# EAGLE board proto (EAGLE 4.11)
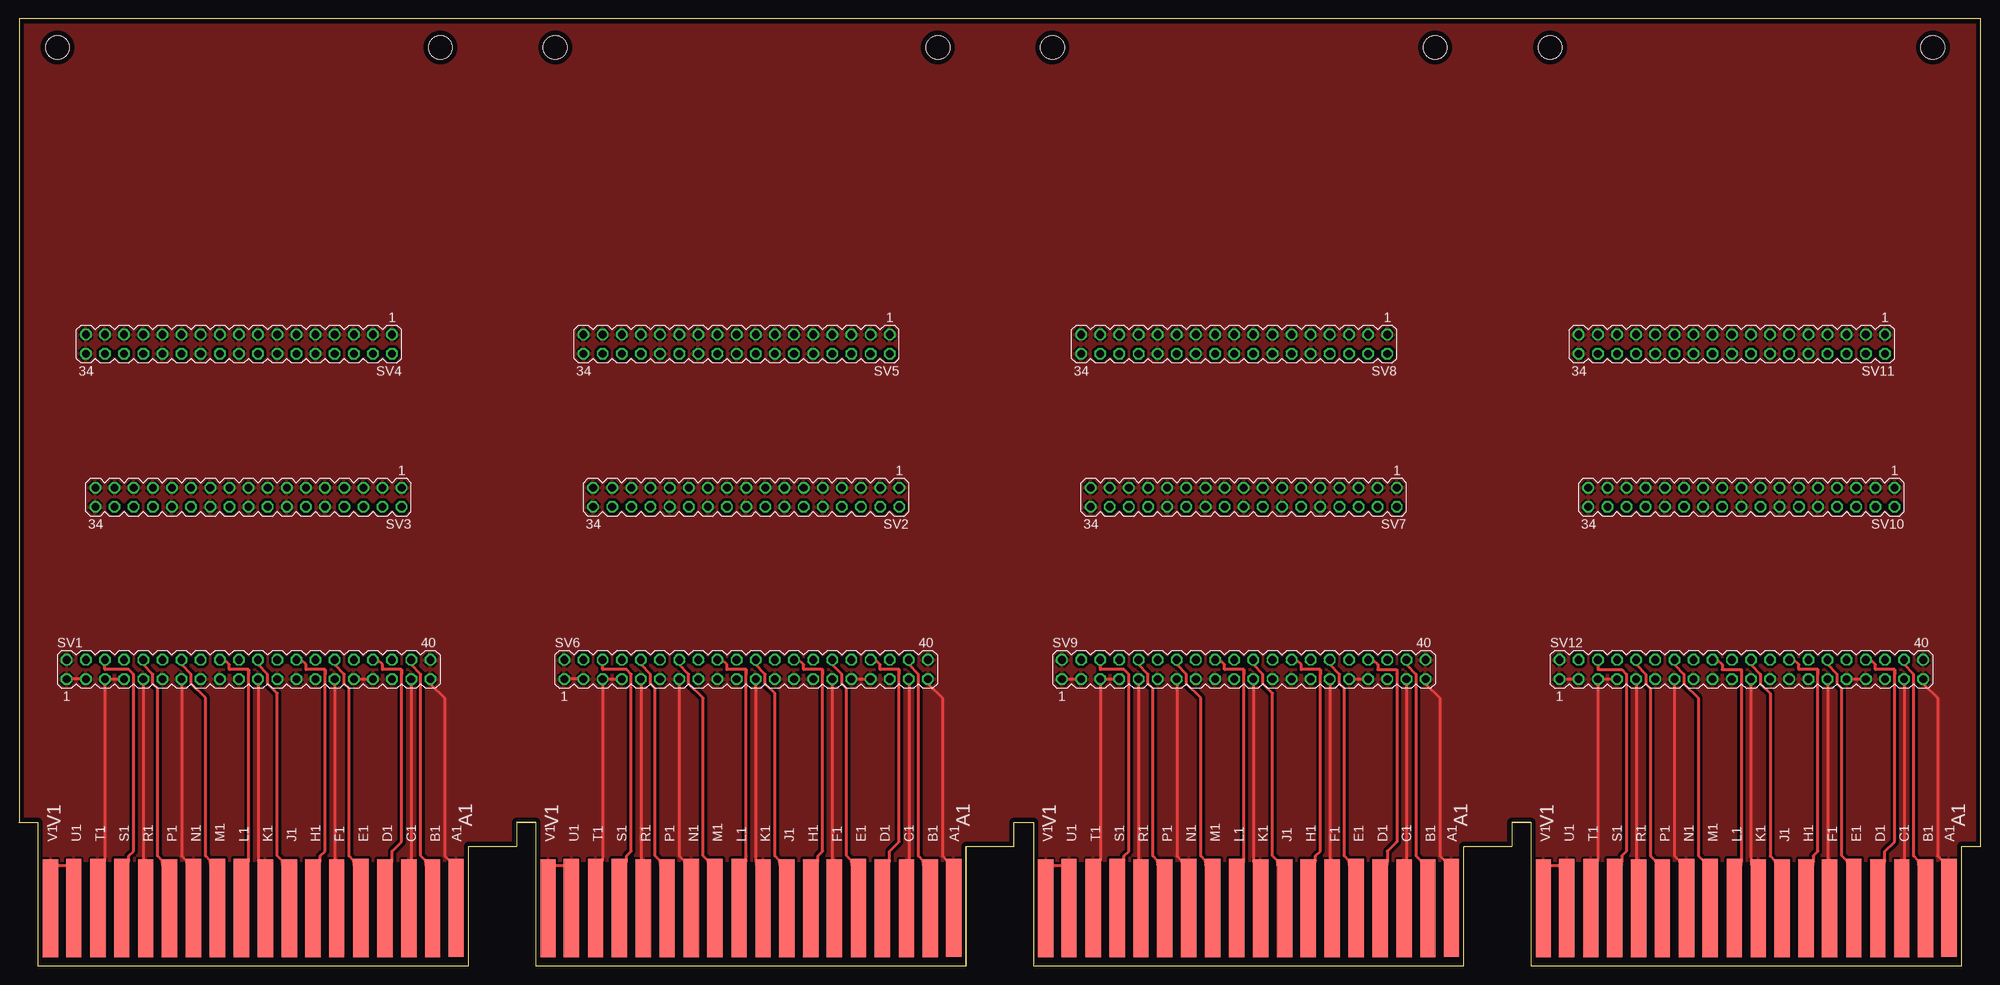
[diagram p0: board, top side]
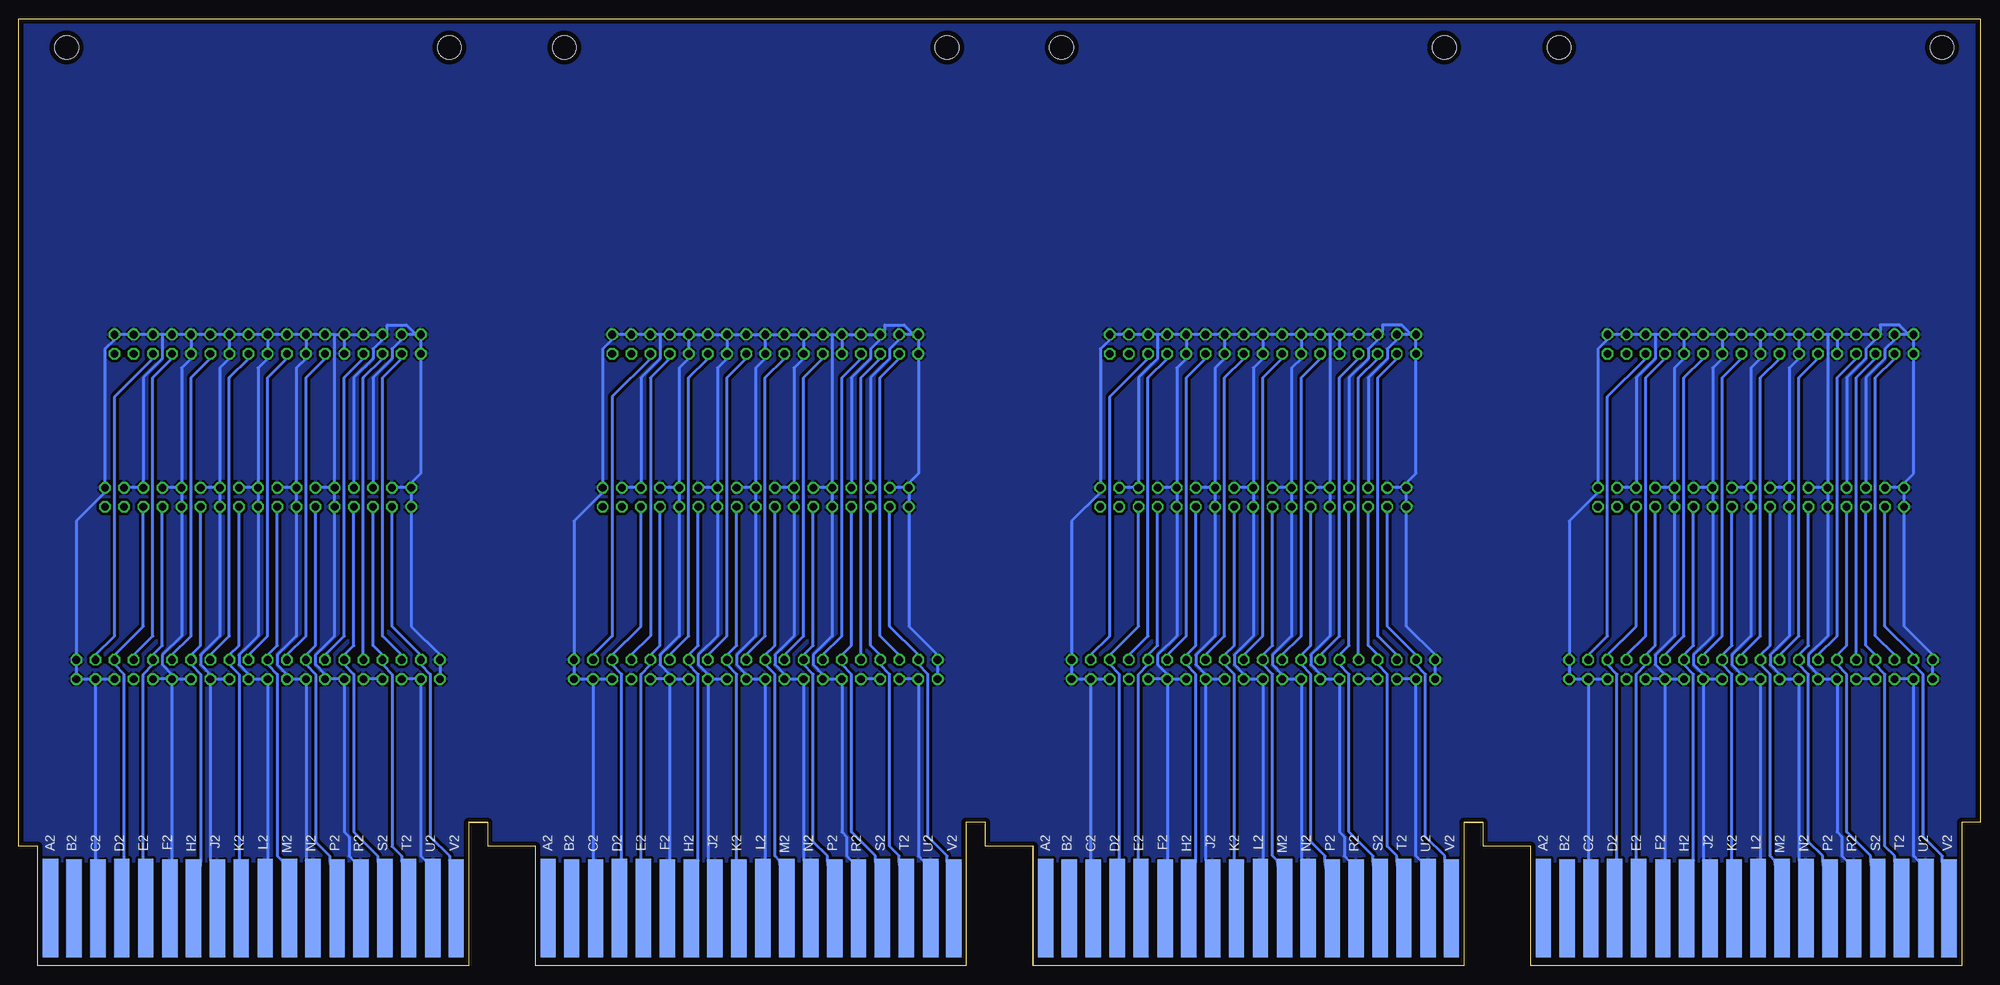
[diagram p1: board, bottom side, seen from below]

Size 260.35 x 125.73 mm. Coordinates in mm from the lower left corner, seen from the top.
Copper layers (1*16): Top 0.035mm / dielectric 1.5mm / Bottom 0.035mm
Design rules "olimex10mil": minimum track width 15mil, minimum drill 24mil, track to track 15mil, track to pad 10mil, pad to pad 10mil, via to via 10mil, smd to smd 10mil, copper to edge 25mil, drill to drill 10mil, minimum pad ring 10mil, minimum via ring 8mil, stop-mask expansion 0mil, vias tented up to drill 0mil, thermal gap 10mil

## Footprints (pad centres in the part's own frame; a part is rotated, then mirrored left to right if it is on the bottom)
DECPROTO = hole 3.175: 203.2,121.92; 254,121.92; 187.96,121.92; 137.16,121.92; 71.171,121.92; 121.971,121.92; 55.931,121.92; 5.131,121.92
MA20-2 = drill 1.016 octagon: 1 -24.13,-1.27; 2 -24.13,1.27; 3 -21.59,-1.27; 4 -21.59,1.27; 5 -19.05,-1.27; 6 -19.05,1.27; 7 -16.51,-1.27; 8 -16.51,1.27; 9 -13.97,-1.27; 10 -13.97,1.27; 11 -11.43,-1.27; 12 -11.43,1.27; 13 -8.89,-1.27; 14 -8.89,1.27; 15 -6.35,-1.27; 16 -6.35,1.27; 17 -3.81,-1.27; 18 -3.81,1.27; 19 -1.27,-1.27; 20 -1.27,1.27; 21 1.27,-1.27; 22 1.27,1.27; 23 3.81,-1.27; 24 3.81,1.27; 25 6.35,-1.27; 26 6.35,1.27; 27 8.89,-1.27; 28 8.89,1.27; 29 11.43,-1.27; 30 11.43,1.27; 31 13.97,-1.27; 32 13.97,1.27; 33 16.51,-1.27; 34 16.51,1.27; 35 19.05,-1.27; 36 19.05,1.27; 37 21.59,-1.27; 38 21.59,1.27; 39 24.13,-1.27; 40 24.13,1.27
MA17-2 = drill 1.016 octagon: 1 -20.32,-1.27; 2 -20.32,1.27; 3 -17.78,-1.27; 4 -17.78,1.27; 5 -15.24,-1.27; 6 -15.24,1.27; 7 -12.7,-1.27; 8 -12.7,1.27; 9 -10.16,-1.27; 10 -10.16,1.27; 11 -7.62,-1.27; 12 -7.62,1.27; 13 -5.08,-1.27; 14 -5.08,1.27; 15 -2.54,-1.27; 16 -2.54,1.27; 17 0,-1.27; 18 0,1.27; 19 2.54,-1.27; 20 2.54,1.27; 21 5.08,-1.27; 22 5.08,1.27; 23 7.62,-1.27; 24 7.62,1.27; 25 10.16,-1.27; 26 10.16,1.27; 27 12.7,-1.27; 28 12.7,1.27; 29 15.24,-1.27; 30 15.24,1.27; 31 17.78,-1.27; 32 17.78,1.27; 33 20.32,-1.27; 34 20.32,1.27
EDGE-CON2 = smd 13.017 x 2.032: A1 7.709,4.207; B1 7.684,7.312; C1 7.684,10.474; D1 7.684,13.665; E1 7.693,16.84; F1 7.668,20.041; H1 7.668,23.19; J1 7.668,26.34; K1 7.668,29.515; L1 7.693,32.69; M1 7.693,35.89; N1 7.693,39.04; P1 7.668,42.24; R1 7.668,45.39; S1 7.693,48.565; T1 7.693,51.74; U1 7.693,54.94; V1 7.668,58.026 | smd 13.017 x 2.032 bottom: A2 7.69,4.207; B2 7.668,7.328; C2 7.668,10.49; D2 7.693,13.665; E2 7.693,16.84; F2 7.642,20.041; H2 7.642,23.19; J2 7.668,26.34; K2 7.668,29.515; L2 7.693,32.69; M2 7.693,35.89; N2 7.693,39.04; P2 7.668,42.24; R2 7.668,45.39; S2 7.693,48.565; T2 7.693,51.74; U2 7.693,54.966; V2 7.668,58.026

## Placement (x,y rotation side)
E$1  [DECPROTO]  0,0 0 top
SV1  [MA20-2]  30.48,39.37 0 top
SV2  [MA17-2]  96.52,62.23 180 top
SV3  [MA17-2]  30.48,62.23 180 top
SV4  [MA17-2]  29.21,82.55 180 top
SV5  [MA17-2]  95.25,82.55 180 top
SV6  [MA20-2]  96.52,39.37 0 top
SV7  [MA17-2]  162.56,62.23 180 top
SV8  [MA17-2]  161.29,82.55 180 top
SV9  [MA20-2]  162.56,39.37 0 top
SV10  [MA17-2]  228.6,62.23 180 top
SV11  [MA17-2]  227.33,82.55 180 top
SV12  [MA20-2]  228.6,39.37 0 top
U$1  [EDGE-CON2]  194.31,0 90 top
U$2  [EDGE-CON2]  62.23,0 90 top
U$3  [EDGE-CON2]  128.27,0 90 top
U$5  [EDGE-CON2]  260.35,0 90 top

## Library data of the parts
E$1 U$1-U$3 U$5 = dec-con
SV1-SV12 = con-lstb

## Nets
-15V: U$2.B2
-15V1: U$3.B2
-15V2: U$1.B2
-15V3: U$5.B2
B1: SV1.38 SV4.6 U$2.B1
B2: SV5.6 SV6.38 U$3.B1
B3: SV8.6 SV9.38 U$1.B1
B4: SV11.6 SV12.38 U$5.B1
D1: SV1.34 SV4.8 U$2.D1
D2: SV1.36 SV3.6 U$2.D2
D3: SV2.6 SV6.36 U$3.D2
D4: SV5.8 SV6.34 U$3.D1
D5: SV7.6 SV9.36 U$1.D2
D6: SV8.8 SV9.34 U$1.D1
D7: SV10.6 SV12.36 U$5.D2
D8: SV11.8 SV12.34 U$5.D1
E1: SV1.30 SV4.12 U$2.E1
E2: SV1.32 SV3.8 U$2.E2
E3: SV2.8 SV6.32 U$3.E2
E4: SV5.12 SV6.30 U$3.E1
E5: SV7.8 SV9.32 U$1.E2
E6: SV8.12 SV9.30 U$1.E1
E7: SV10.8 SV12.32 U$5.E2
E8: SV11.12 SV12.30 U$5.E1
GND: SV1.1 SV1.2 SV1.3 SV1.5 SV1.7 SV1.9 SV1.11 SV1.13 SV1.15 SV1.17 SV1.19 SV1.21 SV1.23 SV1.25 SV1.27 SV1.29 SV1.31 SV1.33 SV1.35 SV1.37 SV1.39 SV1.40 SV2.1 SV2.3 SV2.5 SV2.7 SV2.9 SV2.10 SV2.11 SV2.13 SV2.14 SV2.15 SV2.17 SV2.18 SV2.19 SV2.21 SV2.22 SV2.23 SV2.25 SV2.26 SV2.27 SV2.29 SV2.31 SV2.33 SV2.34 SV3.1 SV3.3 SV3.5 SV3.7 SV3.9 SV3.10 SV3.11 SV3.13 SV3.14 SV3.15 SV3.17 SV3.18 SV3.19 SV3.21 SV3.22 SV3.23 SV3.25 SV3.26 SV3.27 SV3.29 SV3.31 SV3.33 SV3.34 SV4.1 SV4.3 SV4.5 SV4.7 SV4.9 SV4.10 SV4.11 SV4.13 SV4.14 SV4.15 SV4.17 SV4.18 SV4.19 SV4.21 SV4.22 SV4.23 SV4.25 SV4.26 SV4.27 SV4.29 SV4.31 SV4.33 SV4.34 SV5.1 SV5.3 SV5.5 SV5.7 SV5.9 SV5.10 SV5.11 SV5.13 SV5.14 SV5.15 SV5.17 SV5.18 SV5.19 SV5.21 SV5.22 SV5.23 SV5.25 SV5.26 SV5.27 SV5.29 SV5.31 SV5.33 SV5.34 SV6.1 SV6.2 SV6.3 SV6.5 SV6.7 SV6.9 SV6.11 SV6.13 SV6.15 SV6.17 SV6.19 SV6.21 SV6.23 SV6.25 SV6.27 SV6.29 SV6.31 SV6.33 SV6.35 SV6.37 SV6.39 SV6.40 SV7.1 SV7.3 SV7.5 SV7.7 SV7.9 SV7.10 SV7.11 SV7.13 SV7.14 SV7.15 SV7.17 SV7.18 SV7.19 SV7.21 SV7.22 SV7.23 SV7.25 SV7.26 SV7.27 SV7.29 SV7.31 SV7.33 SV7.34 SV8.1 SV8.3 SV8.5 SV8.7 SV8.9 SV8.10 SV8.11 SV8.13 SV8.14 SV8.15 SV8.17 SV8.18 SV8.19 SV8.21 SV8.22 SV8.23 SV8.25 SV8.26 SV8.27 SV8.29 SV8.31 SV8.33 SV8.34 SV9.1 SV9.2 SV9.3 SV9.5 SV9.7 SV9.9 SV9.11 SV9.13 SV9.15 SV9.17 SV9.19 SV9.21 SV9.23 SV9.25 SV9.27 SV9.29 SV9.31 SV9.33 SV9.35 SV9.37 SV9.39 SV9.40 SV10.1 SV10.3 SV10.5 SV10.7 SV10.9 SV10.10 SV10.11 SV10.13 SV10.14 SV10.15 SV10.17 SV10.18 SV10.19 SV10.21 SV10.22 SV10.23 SV10.25 SV10.26 SV10.27 SV10.29 SV10.31 SV10.33 SV10.34 SV11.1 SV11.3 SV11.5 SV11.7 SV11.9 SV11.10 SV11.11 SV11.13 SV11.14 SV11.15 SV11.17 SV11.18 SV11.19 SV11.21 SV11.22 SV11.23 SV11.25 SV11.26 SV11.27 SV11.29 SV11.31 SV11.33 SV11.34 SV12.1 SV12.2 SV12.3 SV12.5 SV12.7 SV12.9 SV12.11 SV12.13 SV12.15 SV12.17 SV12.19 SV12.21 SV12.23 SV12.25 SV12.27 SV12.29 SV12.31 SV12.33 SV12.35 SV12.37 SV12.39 SV12.40 U$1.A1 U$1.C1 U$1.C2 U$1.F1 U$1.F2 U$1.J2 U$1.K1 U$1.L2 U$1.N1 U$1.N2 U$1.R1 U$1.R2 U$1.T1 U$1.U1 U$1.U2 U$1.V1 U$2.A1 U$2.C1 U$2.C2 U$2.F1 U$2.F2 U$2.J2 U$2.K1 U$2.L2 U$2.N1 U$2.N2 U$2.R1 U$2.R2 U$2.T1 U$2.U1 U$2.U2 U$2.V1 U$3.A1 U$3.C1 U$3.C2 U$3.F1 U$3.F2 U$3.J2 U$3.K1 U$3.L2 U$3.N1 U$3.N2 U$3.R1 U$3.R2 U$3.T1 U$3.U1 U$3.U2 U$3.V1 U$5.A1 U$5.C1 U$5.C2 U$5.F1 U$5.F2 U$5.J2 U$5.K1 U$5.L2 U$5.N1 U$5.N2 U$5.R1 U$5.R2 U$5.T1 U$5.U1 U$5.U2 U$5.V1
H1: SV1.26 SV4.16 U$2.H1
H2: SV1.28 SV3.12 U$2.H2
H3: SV2.12 SV6.28 U$3.H2
H4: SV5.16 SV6.26 U$3.H1
H5: SV7.12 SV9.28 U$1.H2
H6: SV8.16 SV9.26 U$1.H1
H7: SV10.12 SV12.28 U$5.H2
H8: SV11.16 SV12.26 U$5.H1
J1: SV1.22 SV4.20 U$2.J1
J2: SV5.20 SV6.22 U$3.J1
J3: SV8.20 SV9.22 U$1.J1
J4: SV11.20 SV12.22 U$5.J1
K1: SV2.16 SV6.24 U$3.K2
K2: SV1.24 SV3.16 U$2.K2
K3: SV7.16 SV9.24 U$1.K2
K4: SV10.16 SV12.24 U$5.K2
L1: SV1.18 SV4.24 U$2.L1
L2: SV5.24 SV6.18 U$3.L1
L3: SV8.24 SV9.18 U$1.L1
L4: SV11.24 SV12.18 U$5.L1
M1: SV1.14 SV4.28 U$2.M1
M2: SV1.20 SV3.20 U$2.M2
M3: SV2.20 SV6.20 U$3.M2
M4: SV5.28 SV6.14 U$3.M1
M5: SV7.20 SV9.20 U$1.M2
M6: SV8.28 SV9.14 U$1.M1
M7: SV10.20 SV12.20 U$5.M2
M8: SV11.28 SV12.14 U$5.M1
P1: SV1.10 SV4.30 U$2.P1
P2: SV1.16 SV3.24 U$2.P2
P3: SV2.24 SV6.16 U$3.P2
P4: SV5.30 SV6.10 U$3.P1
P5: SV7.24 SV9.16 U$1.P2
P6: SV8.30 SV9.10 U$1.P1
P7: SV10.24 SV12.16 U$5.P2
P8: SV11.30 SV12.10 U$5.P1
S1: SV1.6 SV4.32 U$2.S1
S2: SV1.12 SV3.28 U$2.S2
S3: SV2.28 SV6.12 U$3.S2
S4: SV5.32 SV6.6 U$3.S1
S5: SV7.28 SV9.12 U$1.S2
S6: SV8.32 SV9.6 U$1.S1
S7: SV10.28 SV12.12 U$5.S2
S8: SV11.32 SV12.6 U$5.S1
T1: SV2.30 SV6.8 U$3.T2
T2: SV1.8 SV3.30 U$2.T2
T3: SV7.30 SV9.8 U$1.T2
T4: SV10.30 SV12.8 U$5.T2
V1: SV2.32 SV6.4 U$3.V2
V2: SV1.4 SV3.32 U$2.V2
V3: SV7.32 SV9.4 U$1.V2
V4: SV10.32 SV12.4 U$5.V2
VCC: U$2.A2
VCC1: U$3.A2
VCC2: U$1.A2
VCC3: U$5.A2

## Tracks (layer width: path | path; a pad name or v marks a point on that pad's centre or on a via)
B1
  Top 0.381: SV1.38 52.07,40.01 53.34,38.74 53.34,14.61 53.98,13.97 U$2.B1
  Bottom 0.381: SV1.38 52.07,41.28 49.53,43.82 49.53,75.57 44.45,80.65 SV4.6
B2
  Top 0.381: SV6.38 118.11,40.01 119.38,38.74 119.38,14.61 120.02,13.97 U$3.B1
  Bottom 0.381: SV6.38 118.11,41.28 115.57,43.82 115.57,75.57 110.49,80.65 SV5.6
B3
  Top 0.381: SV9.38 184.15,40.01 185.42,38.74 185.42,14.61 186.06,13.97 U$1.B1
  Bottom 0.381: SV9.38 184.15,41.28 181.61,43.82 181.61,75.57 176.53,80.65 SV8.6
B4
  Top 0.381: SV12.38 250.19,40.01 251.46,38.74 251.46,14.61 252.09,13.97 U$5.B1
  Bottom 0.381: SV12.38 250.19,41.28 247.65,43.82 247.65,75.57 242.57,80.65 SV11.6
D1
  Top 0.381: 50.8,39.37 50.8,16.51 49.53,15.24 49.53,13.97 U$2.D1 | 50.8,39.37 50.8,38.74 | 50.8,39.37 48.26,39.37 48.26,40.01 47.62,40.64 SV1.34
  Bottom 0.381: SV1.34 46.99,41.28 44.45,43.82 44.45,78.11 41.91,80.65 SV4.8
D2
  Bottom 0.381: SV3.6 45.72,60.33 45.72,45.09 49.53,41.28 SV1.36 49.53,40.01 48.26,38.74 48.26,13.97 U$2.D2
D3
  Bottom 0.381: SV2.6 111.76,60.33 111.76,45.09 115.57,41.28 SV6.36 115.57,40.01 114.3,38.74 114.3,13.97 U$3.D2
D4
  Top 0.381: 116.84,39.37 116.84,16.51 115.57,15.24 115.57,13.97 U$3.D1 | 116.84,39.37 116.84,38.74 | 116.84,39.37 114.3,39.37 114.3,40.01 113.67,40.64 SV6.34
  Bottom 0.381: SV6.34 113.03,41.28 110.49,43.82 110.49,78.11 107.95,80.65 SV5.8
D5
  Bottom 0.381: SV7.6 177.8,60.33 177.8,45.09 181.61,41.28 SV9.36 181.61,40.01 180.34,38.74 180.34,13.97 U$1.D2
D6
  Top 0.381: 182.88,39.37 182.88,16.51 181.61,15.24 181.61,13.97 U$1.D1 | 182.88,39.37 182.88,38.74 | 182.88,39.37 180.34,39.37 180.34,40.01 179.71,40.64 SV9.34
  Bottom 0.381: SV9.34 179.07,41.28 176.53,43.82 176.53,78.11 173.99,80.65 SV8.8
D7
  Bottom 0.381: SV10.6 243.84,60.33 243.84,45.09 247.65,41.28 SV12.36 247.65,40.01 246.38,38.74 246.38,13.97 U$5.D2
D8
  Top 0.381: 248.92,39.37 248.92,16.51 247.65,15.24 247.65,13.97 U$5.D1 | 248.92,39.37 248.92,38.74 | 248.92,39.37 246.38,39.37 246.38,40.01 245.75,40.64 SV12.34
  Bottom 0.381: SV12.34 245.11,41.28 242.57,43.82 242.57,78.11 240.03,80.65 SV11.8
E1
  Top 0.381: SV1.30 41.91,40.01 43.18,38.74 43.18,37.47 43.81,36.83 43.81,14.61 44.45,13.97 U$2.E1
  Bottom 0.381: SV1.30 41.91,41.28 39.37,43.82 39.37,78.11 36.83,80.65 SV4.12
E2
  Bottom 0.381: SV3.8 43.18,60.33 43.18,42.55 44.45,41.28 SV1.32 44.45,40.01 45.72,38.74 45.72,13.97 U$2.E2
E3
  Bottom 0.381: SV2.8 109.22,60.33 109.22,42.55 110.49,41.28 SV6.32 110.49,40.01 111.76,38.74 111.76,13.97 U$3.E2
E4
  Top 0.381: SV6.30 107.95,40.01 109.22,38.74 109.22,37.47 109.86,36.83 109.86,14.61 110.49,13.97 U$3.E1
  Bottom 0.381: SV6.30 107.95,41.28 105.41,43.82 105.41,78.11 102.87,80.65 SV5.12
E5
  Bottom 0.381: SV7.8 175.26,60.33 175.26,42.55 176.53,41.28 SV9.32 176.53,40.01 177.8,38.74 177.8,13.97 U$1.E2
E6
  Top 0.381: SV9.30 173.99,40.01 175.26,38.74 175.26,37.47 175.9,36.83 175.9,14.61 176.53,13.97 U$1.E1
  Bottom 0.381: SV9.30 173.99,41.28 171.45,43.82 171.45,78.11 168.91,80.65 SV8.12
E7
  Bottom 0.381: SV10.8 241.3,60.33 241.3,42.55 242.57,41.28 SV12.32 242.57,40.01 243.84,38.74 243.84,13.97 U$5.E2
E8
  Top 0.381: SV12.30 240.03,40.01 241.3,38.74 241.3,37.47 241.94,36.83 241.94,14.61 242.57,13.97 U$5.E1
  Bottom 0.381: SV12.30 240.03,41.28 237.49,43.82 237.49,78.11 234.95,80.65 SV11.12
GND
  Top 0.381: 11.43,13.97 11.43,37.47 SV1.5 12.06,38.1 13.34,38.1 SV1.7 | SV1.9 16.51,37.47 16.51,13.97 U$2.R1 | SV1.3 8.26,38.1 6.99,38.1 SV1.1 | 52.07,13.97 52.07,37.47 SV1.37 | SV1.39 54.61,37.47 56.52,35.56 56.52,14.61 57.15,13.97 U$2.A1 | SV1.21 31.75,37.47 31.75,13.97 U$2.K1 | SV1.33 46.35,38.1 45.09,38.1 SV1.31 | SV1.29 41.91,37.47 41.91,13.97 U$2.F1 | SV1.13 21.59,37.47 21.59,14.61 22.23,13.97 U$2.N1 | 4,13.97 3.81,13.97 U$2.V1 5.08,13.34 6.35,13.34 U$2.U1 | U$2.T1 10.16,13.97 10.29,13.97 | U$2.C1 51.44,13.97 51.55,13.97 | 77.47,13.97 77.47,37.47 SV6.5 78.11,38.1 79.38,38.1 SV6.7 | SV6.9 82.55,37.47 82.55,13.97 U$3.R1 | SV6.3 74.3,38.1 73.03,38.1 SV6.1 | 118.11,13.97 118.11,37.47 SV6.37 | SV6.39 120.65,37.47 122.56,35.56 122.56,14.61 123.19,13.97 U$3.A1 | SV6.21 97.79,37.47 97.79,13.97 U$3.K1 | SV6.33 112.39,38.1 111.12,38.1 SV6.31 | SV6.29 107.95,37.47 107.95,13.97 U$3.F1 | SV6.13 87.63,37.47 87.63,14.61 88.27,13.97 U$3.N1 | 70.04,13.97 69.85,13.97 U$3.V1 71.12,13.34 72.39,13.34 U$3.U1 | U$3.T1 76.2,13.97 76.33,13.97 | U$3.C1 117.47,13.97 117.59,13.97 | 143.51,13.97 143.51,37.47 SV9.5 144.15,38.1 145.41,38.1 SV9.7 | SV9.9 148.59,37.47 148.59,13.97 U$1.R1 | SV9.3 140.34,38.1 139.06,38.1 SV9.1 | 184.15,13.97 184.15,37.47 SV9.37 | SV9.39 186.69,37.47 188.59,35.56 188.59,14.61 189.23,13.97 U$1.A1 | SV9.21 163.83,37.47 163.83,13.97 U$1.K1 | SV9.33 178.44,38.1 177.16,38.1 SV9.31 | SV9.29 173.99,37.47 173.99,13.97 U$1.F1 | SV9.13 153.67,37.47 153.67,14.61 154.31,13.97 U$1.N1 | 136.08,13.97 135.89,13.97 U$1.V1 137.16,13.34 138.43,13.34 U$1.U1 | U$1.T1 142.24,13.97 142.37,13.97 | U$1.C1 183.51,13.97 183.63,13.97
  Top 0.381: 209.55,13.97 209.55,37.47 SV12.5 210.19,38.1 211.46,38.1 SV12.7 | SV12.9 214.63,37.47 214.63,13.97 U$5.R1 | SV12.3 206.38,38.1 205.1,38.1 SV12.1 | 250.19,13.97 250.19,37.47 SV12.37 | SV12.39 252.73,37.47 254.63,35.56 254.63,14.61 255.27,13.97 U$5.A1 | SV12.21 229.87,37.47 229.87,13.97 U$5.K1 | SV12.33 244.47,38.1 243.21,38.1 SV12.31 | SV12.29 240.03,37.47 240.03,13.97 U$5.F1 | SV12.13 219.71,37.47 219.71,14.61 220.34,13.97 U$5.N1 | 202.12,13.97 201.93,13.97 U$5.V1 203.2,13.34 204.47,13.34 U$5.U1 | U$5.T1 208.28,13.97 208.41,13.97 | U$5.C1 249.56,13.97 249.67,13.97
  Bottom 0.381: SV1.5 10.79,38.1 9.53,38.1 SV1.3 8.89,37.47 8.89,14.61 8.26,13.97 | SV1.9 15.88,38.1 14.61,38.1 SV1.7 | SV1.1 6.35,38.74 6.35,40.01 SV1.2 6.35,41.28 10.16,45.09 10.16,60.33 SV3.34 10.16,61.6 10.16,62.87 SV3.33 | SV3.31 12.06,63.5 10.79,63.5 SV3.33 | SV4.33 8.89,83.19 8.89,81.92 SV4.34 8.89,80.65 8.89,65.41 10.16,64.14 SV3.33 | SV3.29 15.24,64.14 15.24,78.11 12.7,80.65 12.7,81.92 11.43,83.19 SV4.31 10.79,83.82 9.53,83.82 | SV4.33 9.53,83.82 | SV1.37 52.7,38.1 53.98,38.1 SV1.39 54.61,38.74 54.61,40.01 SV1.40 54.61,41.28 54.61,59.06 50.8,62.87 SV3.1 50.8,64.14 50.8,81.92 49.53,83.19 SV4.1 48.9,83.82 47.62,83.82 SV4.3 46.35,83.82 45.09,83.82 SV4.5 43.81,83.82 43.18,83.82 | SV1.35 50.16,38.1 51.44,38.1 SV1.37 | 52.07,13.97 52.07,37.47 SV1.37 | SV1.29 42.55,38.1 43.81,38.1 SV1.31 | SV1.27 40.01,38.1 41.27,38.1 SV1.29 | SV1.29 41.91,37.47 41.91,13.97 U$2.F2 | SV1.25 36.2,38.1 34.92,38.1 SV1.23 | 36.83,13.97 36.83,37.47 SV1.25 | 24.13,13.97 24.13,37.47 SV1.15 24.77,38.1 26.04,38.1 SV1.17 26.67,38.74 27.94,40.01 27.94,41.28 25.4,43.82 25.4,60.33 SV3.22 25.4,61.6 25.4,62.87 SV3.21 | SV3.13 35.56,62.87 35.56,61.6 SV3.14 35.56,60.33 35.56,43.82 38.1,41.28 38.1,40.01 36.83,38.74 SV1.25 | SV3.11 37.47,63.5 36.2,63.5 SV3.13 | SV4.13 34.29,83.19 34.29,81.92 SV4.14 34.29,80.65 35.56,79.38 35.56,64.14 SV3.13 | SV4.13 33.66,83.82 32.38,83.82 SV4.15 31.11,83.82 29.84,83.82 SV4.17 | SV3.17 30.48,62.87 30.48,61.6 SV3.18 30.48,60.33 30.48,43.82 33.02,41.28 33.02,40.01 31.75,38.74 SV1.21 31.11,38.1 29.84,38.1 SV1.19 29.21,37.47 29.21,13.97 U$2.L2 | SV3.15 32.38,63.5 31.11,63.5 SV3.17
  Bottom 0.381: SV4.17 29.21,83.19 29.21,81.92 SV4.18 29.21,80.65 30.48,79.38 30.48,64.14 SV3.17 | SV4.17 28.57,83.82 27.3,83.82 SV4.19 26.04,83.82 24.77,83.82 SV4.21 | SV3.3 47.62,63.5 46.35,63.5 SV3.5 45.72,64.14 45.72,78.11 43.18,80.65 43.18,83.82 | 43.18,83.82 42.55,83.82 SV4.7 41.27,83.82 40.01,83.82 SV4.9 | SV3.9 40.64,62.87 40.64,61.6 SV3.10 40.64,60.33 40.64,43.82 43.18,41.28 43.18,40.01 41.91,38.74 SV1.29 | SV3.7 42.55,63.5 41.27,63.5 SV3.9 | SV4.9 39.37,83.19 39.37,81.92 SV4.10 39.37,80.65 40.64,79.38 40.64,64.14 SV3.9 | SV4.9 38.73,83.82 37.47,83.82 SV4.11 36.2,83.82 34.92,83.82 SV4.13 | SV3.23 22.23,63.5 20.95,63.5 SV3.25 | SV3.25 20.32,62.87 20.32,61.6 SV3.26 20.32,60.33 20.32,43.82 22.86,41.28 22.86,40.01 21.59,38.74 SV1.13 20.95,38.1 19.68,38.1 SV1.11 19.05,37.47 19.05,17.78 18.41,17.15 18.41,14.61 17.78,13.97 | SV4.26 19.05,81.92 19.05,83.19 SV4.25 | SV4.25 18.41,83.82 17.14,83.82 SV4.27 15.88,83.82 14.61,83.82 SV4.29 | SV3.27 17.78,64.14 17.78,78.11 15.24,80.65 15.24,81.92 13.97,83.19 SV4.29 | SV3.19 27.3,63.5 26.04,63.5 SV3.21 | SV4.21 24.13,83.19 24.13,81.92 SV4.22 24.13,80.65 25.4,79.38 25.4,64.14 SV3.21 | SV4.21 23.5,83.82 22.23,83.82 SV4.23 20.95,83.82 20.32,83.82 | 20.32,83.82 19.68,83.82 SV4.25 | 20.32,83.82 20.32,64.14 SV3.25 | 9.53,83.82 10.79,85.09 13.34,85.09 13.34,83.82 SV4.29 | SV4.33 9.53,83.82 | U$2.U2 6.99,13.97 7.06,13.97 | U$2.R1 16.51,13.97 16.64,13.97 | U$2.N1 22.86,13.97 22.99,13.97 | U$2.J2 35.56,13.97 35.69,13.97 | U$2.C2 51.44,13.97 51.54,13.97 | SV6.5 76.83,38.1 75.56,38.1 SV6.3 74.93,37.47 74.93,14.61 74.3,13.97 | SV6.9 81.92,38.1 80.64,38.1 SV6.7
  Bottom 0.381: SV6.1 72.39,38.74 72.39,40.01 SV6.2 72.39,41.28 76.2,45.09 76.2,60.33 SV2.34 76.2,61.6 76.2,62.87 SV2.33 | SV2.31 78.11,63.5 76.83,63.5 SV2.33 | SV5.33 74.93,83.19 74.93,81.92 SV5.34 74.93,80.65 74.93,65.41 76.2,64.14 SV2.33 | SV2.29 81.28,64.14 81.28,78.11 78.74,80.65 78.74,81.92 77.47,83.19 SV5.31 76.83,83.82 75.56,83.82 | SV5.33 75.56,83.82 | SV6.37 118.75,38.1 120.02,38.1 SV6.39 120.65,38.74 120.65,40.01 SV6.40 120.65,41.28 120.65,59.06 116.84,62.87 SV2.1 116.84,64.14 116.84,81.92 115.57,83.19 SV5.1 114.94,83.82 113.67,83.82 SV5.3 112.39,83.82 111.12,83.82 SV5.5 109.86,83.82 109.22,83.82 | SV6.35 116.2,38.1 117.47,38.1 SV6.37 | 118.11,13.97 118.11,37.47 SV6.37 | SV6.29 108.58,38.1 109.86,38.1 SV6.31 | SV6.27 106.05,38.1 107.31,38.1 SV6.29 | SV6.29 107.95,37.47 107.95,13.97 U$3.F2 | SV6.25 102.23,38.1 100.97,38.1 SV6.23 | 102.87,13.97 102.87,37.47 SV6.25 | 90.17,13.97 90.17,37.47 SV6.15 90.81,38.1 92.08,38.1 SV6.17 92.71,38.74 93.98,40.01 93.98,41.28 91.44,43.82 91.44,60.33 SV2.22 91.44,61.6 91.44,62.87 SV2.21 | SV2.13 101.6,62.87 101.6,61.6 SV2.14 101.6,60.33 101.6,43.82 104.14,41.28 104.14,40.01 102.87,38.74 SV6.25 | SV2.11 103.5,63.5 102.23,63.5 SV2.13 | SV5.13 100.33,83.19 100.33,81.92 SV5.14 100.33,80.65 101.6,79.38 101.6,64.14 SV2.13 | SV5.13 99.69,83.82 98.42,83.82 SV5.15 97.16,83.82 95.89,83.82 SV5.17 | SV2.17 96.52,62.87 96.52,61.6 SV2.18 96.52,60.33 96.52,43.82 99.06,41.28 99.06,40.01 97.79,38.74 SV6.21 97.16,38.1 95.89,38.1 SV6.19 95.25,37.47 95.25,13.97 U$3.L2 | SV2.15 98.42,63.5 97.16,63.5 SV2.17 | SV5.17 95.25,83.19 95.25,81.92 SV5.18 95.25,80.65 96.52,79.38 96.52,64.14 SV2.17
  Bottom 0.381: SV5.17 94.61,83.82 93.34,83.82 SV5.19 92.08,83.82 90.81,83.82 SV5.21 | SV2.3 113.67,63.5 112.39,63.5 SV2.5 111.76,64.14 111.76,78.11 109.22,80.65 109.22,83.82 | 109.22,83.82 108.58,83.82 SV5.7 107.31,83.82 106.05,83.82 SV5.9 | SV2.9 106.68,62.87 106.68,61.6 SV2.10 106.68,60.33 106.68,43.82 109.22,41.28 109.22,40.01 107.95,38.74 SV6.29 | SV2.7 108.58,63.5 107.31,63.5 SV2.9 | SV5.9 105.41,83.19 105.41,81.92 SV5.10 105.41,80.65 106.68,79.38 106.68,64.14 SV2.9 | SV5.9 104.78,83.82 103.5,83.82 SV5.11 102.23,83.82 100.97,83.82 SV5.13 | SV2.23 88.27,63.5 87,63.5 SV2.25 | SV2.25 86.36,62.87 86.36,61.6 SV2.26 86.36,60.33 86.36,43.82 88.9,41.28 88.9,40.01 87.63,38.74 SV6.13 87,38.1 85.72,38.1 SV6.11 85.09,37.47 85.09,17.78 84.45,17.15 84.45,14.61 83.82,13.97 | SV5.26 85.09,81.92 85.09,83.19 SV5.25 | SV5.25 84.45,83.82 83.19,83.82 SV5.27 81.92,83.82 80.64,83.82 SV5.29 | SV2.27 83.82,64.14 83.82,78.11 81.28,80.65 81.28,81.92 80.01,83.19 SV5.29 | SV2.19 93.34,63.5 92.08,63.5 SV2.21 | SV5.21 90.17,83.19 90.17,81.92 SV5.22 90.17,80.65 91.44,79.38 91.44,64.14 SV2.21 | SV5.21 89.53,83.82 88.27,83.82 SV5.23 87,83.82 86.36,83.82 | 86.36,83.82 85.72,83.82 SV5.25 | 86.36,83.82 86.36,64.14 SV2.25 | 75.56,83.82 76.83,85.09 79.38,85.09 79.38,83.82 SV5.29 | SV5.33 75.56,83.82 | U$3.U2 73.03,13.97 73.1,13.97 | U$3.R1 82.55,13.97 82.68,13.97 | U$3.N1 88.9,13.97 89.03,13.97 | U$3.J2 101.6,13.97 101.73,13.97 | U$3.C2 117.47,13.97 117.58,13.97 | SV9.5 142.88,38.1 141.6,38.1 SV9.3 140.97,37.47 140.97,14.61 140.34,13.97 | SV9.9 147.96,38.1 146.69,38.1 SV9.7 | SV9.1 138.43,38.74 138.43,40.01 SV9.2 138.43,41.28 142.24,45.09 142.24,60.33 SV7.34 142.24,61.6 142.24,62.87 SV7.33
  Bottom 0.381: SV7.31 144.15,63.5 142.88,63.5 SV7.33 | SV8.33 140.97,83.19 140.97,81.92 SV8.34 140.97,80.65 140.97,65.41 142.24,64.14 SV7.33 | SV7.29 147.32,64.14 147.32,78.11 144.78,80.65 144.78,81.92 143.51,83.19 SV8.31 142.88,83.82 141.6,83.82 | 141.6,83.82 SV8.33 | SV9.37 184.78,38.1 186.06,38.1 SV9.39 186.69,38.74 186.69,40.01 SV9.40 186.69,41.28 186.69,59.06 182.88,62.87 SV7.1 182.88,64.14 182.88,81.92 181.61,83.19 SV8.1 180.97,83.82 179.71,83.82 SV8.3 178.44,83.82 177.16,83.82 SV8.5 175.9,83.82 175.26,83.82 | SV9.35 182.25,38.1 183.51,38.1 SV9.37 | 184.15,13.97 184.15,37.47 SV9.37 | SV9.29 174.62,38.1 175.9,38.1 SV9.31 | SV9.27 172.09,38.1 173.35,38.1 SV9.29 | SV9.29 173.99,37.47 173.99,13.97 U$1.F2 | SV9.25 168.28,38.1 167,38.1 SV9.23 | 168.91,13.97 168.91,37.47 SV9.25 | 156.21,13.97 156.21,37.47 SV9.15 156.84,38.1 158.12,38.1 SV9.17 158.75,38.74 160.02,40.01 160.02,41.28 157.48,43.82 157.48,60.33 SV7.22 157.48,61.6 157.48,62.87 SV7.21 | SV7.13 167.64,62.87 167.64,61.6 SV7.14 167.64,60.33 167.64,43.82 170.18,41.28 170.18,40.01 168.91,38.74 SV9.25 | SV7.11 169.54,63.5 168.28,63.5 SV7.13 | SV8.13 166.37,83.19 166.37,81.92 SV8.14 166.37,80.65 167.64,79.38 167.64,64.14 SV7.13 | SV8.13 165.74,83.82 164.47,83.82 SV8.15 163.19,83.82 161.93,83.82 SV8.17 | SV7.17 162.56,62.87 162.56,61.6 SV7.18 162.56,60.33 162.56,43.82 165.1,41.28 165.1,40.01 163.83,38.74 SV9.21 163.19,38.1 161.93,38.1 SV9.19 161.29,37.47 161.29,13.97 U$1.L2 | SV7.15 164.47,63.5 163.19,63.5 SV7.17 | SV8.17 161.29,83.19 161.29,81.92 SV8.18 161.29,80.65 162.56,79.38 162.56,64.14 SV7.17
  Bottom 0.381: SV8.17 160.66,83.82 159.38,83.82 SV8.19 158.12,83.82 156.84,83.82 SV8.21 | SV7.3 179.71,63.5 178.44,63.5 SV7.5 177.8,64.14 177.8,78.11 175.26,80.65 175.26,83.82 | 175.26,83.82 174.62,83.82 SV8.7 173.35,83.82 172.09,83.82 SV8.9 | SV7.9 172.72,62.87 172.72,61.6 SV7.10 172.72,60.33 172.72,43.82 175.26,41.28 175.26,40.01 173.99,38.74 SV9.29 | SV7.7 174.62,63.5 173.35,63.5 SV7.9 | SV8.9 171.45,83.19 171.45,81.92 SV8.10 171.45,80.65 172.72,79.38 172.72,64.14 SV7.9 | SV8.9 170.81,83.82 169.54,83.82 SV8.11 168.28,83.82 167,83.82 SV8.13 | SV7.23 154.31,63.5 153.03,63.5 SV7.25 | SV7.25 152.4,62.87 152.4,61.6 SV7.26 152.4,60.33 152.4,43.82 154.94,41.28 154.94,40.01 153.67,38.74 SV9.13 153.03,38.1 151.76,38.1 SV9.11 151.13,37.47 151.13,17.78 150.5,17.15 150.5,14.61 149.86,13.97 | SV8.26 151.13,81.92 151.13,83.19 SV8.25 | SV8.25 150.5,83.82 149.22,83.82 SV8.27 147.96,83.82 146.69,83.82 SV8.29 | SV7.27 149.86,64.14 149.86,78.11 147.32,80.65 147.32,81.92 146.05,83.19 SV8.29 | SV7.19 159.38,63.5 158.12,63.5 SV7.21 | SV8.21 156.21,83.19 156.21,81.92 SV8.22 156.21,80.65 157.48,79.38 157.48,64.14 SV7.21 | SV8.21 155.57,83.82 154.31,83.82 SV8.23 153.03,83.82 152.4,83.82 | 152.4,83.82 151.76,83.82 SV8.25 | 152.4,83.82 152.4,64.14 SV7.25 | 141.6,83.82 142.88,85.09 145.41,85.09 145.41,83.82 SV8.29 | 141.6,83.82 SV8.33 | U$1.U2 139.06,13.97 139.14,13.97 | U$1.R1 148.59,13.97 148.72,13.97 | U$1.N1 154.94,13.97 155.07,13.97 | U$1.J2 167.64,13.97 167.77,13.97 | U$1.C2 183.51,13.97 183.62,13.97 | SV12.5 208.91,38.1 207.65,38.1 SV12.3 207.01,37.47 207.01,14.61 206.38,13.97 | SV12.9 214,38.1 212.72,38.1 SV12.7
  Bottom 0.381: SV12.1 204.47,38.74 204.47,40.01 SV12.2 204.47,41.28 208.28,45.09 208.28,60.33 SV10.34 208.28,61.6 208.28,62.87 SV10.33 | SV10.31 210.19,63.5 208.91,63.5 SV10.33 | SV11.33 207.01,83.19 207.01,81.92 SV11.34 207.01,80.65 207.01,65.41 208.28,64.14 SV10.33 | SV10.29 213.36,64.14 213.36,78.11 210.82,80.65 210.82,81.92 209.55,83.19 SV11.31 208.91,83.82 207.65,83.82 | 207.65,83.82 SV11.33 | SV12.37 250.82,38.1 252.09,38.1 SV12.39 252.73,38.74 252.73,40.01 SV12.40 252.73,41.28 252.73,59.06 248.92,62.87 SV10.1 248.92,64.14 248.92,81.92 247.65,83.19 SV11.1 247.01,83.82 245.75,83.82 SV11.3 244.47,83.82 243.21,83.82 SV11.5 241.94,83.82 241.3,83.82 | SV12.35 248.28,38.1 249.56,38.1 SV12.37 | 250.19,13.97 250.19,37.47 SV12.37 | SV12.29 240.66,38.1 241.94,38.1 SV12.31 | SV12.27 238.12,38.1 239.4,38.1 SV12.29 | SV12.29 240.03,37.47 240.03,13.97 U$5.F2 | SV12.25 234.31,38.1 233.04,38.1 SV12.23 | 234.95,13.97 234.95,37.47 SV12.25 | 222.25,13.97 222.25,37.47 SV12.15 222.88,38.1 224.16,38.1 SV12.17 224.79,38.74 226.06,40.01 226.06,41.28 223.52,43.82 223.52,60.33 SV10.22 223.52,61.6 223.52,62.87 SV10.21 | SV10.13 233.68,62.87 233.68,61.6 SV10.14 233.68,60.33 233.68,43.82 236.22,41.28 236.22,40.01 234.95,38.74 SV12.25 | SV10.11 235.59,63.5 234.31,63.5 SV10.13 | SV11.13 232.41,83.19 232.41,81.92 SV11.14 232.41,80.65 233.68,79.38 233.68,64.14 SV10.13 | SV11.13 231.78,83.82 230.5,83.82 SV11.15 229.24,83.82 227.97,83.82 SV11.17 | SV10.17 228.6,62.87 228.6,61.6 SV10.18 228.6,60.33 228.6,43.82 231.14,41.28 231.14,40.01 229.87,38.74 SV12.21 229.24,38.1 227.97,38.1 SV12.19 227.33,37.47 227.33,13.97 U$5.L2
  Bottom 0.381: SV10.15 230.5,63.5 229.24,63.5 SV10.17 | SV11.17 227.33,83.19 227.33,81.92 SV11.18 227.33,80.65 228.6,79.38 228.6,64.14 SV10.17 | SV11.17 226.69,83.82 225.43,83.82 SV11.19 224.16,83.82 222.88,83.82 SV11.21 | SV10.3 245.75,63.5 244.47,63.5 SV10.5 243.84,64.14 243.84,78.11 241.3,80.65 241.3,83.82 | 241.3,83.82 240.66,83.82 SV11.7 239.4,83.82 238.12,83.82 SV11.9 | SV10.9 238.76,62.87 238.76,61.6 SV10.10 238.76,60.33 238.76,43.82 241.3,41.28 241.3,40.01 240.03,38.74 SV12.29 | SV10.7 240.66,63.5 239.4,63.5 SV10.9 | SV11.9 237.49,83.19 237.49,81.92 SV11.10 237.49,80.65 238.76,79.38 238.76,64.14 SV10.9 | SV11.9 236.85,83.82 235.59,83.82 SV11.11 234.31,83.82 233.04,83.82 SV11.13 | SV10.23 220.34,63.5 219.07,63.5 SV10.25 | SV10.25 218.44,62.87 218.44,61.6 SV10.26 218.44,60.33 218.44,43.82 220.98,41.28 220.98,40.01 219.71,38.74 SV12.13 219.07,38.1 217.81,38.1 SV12.11 217.17,37.47 217.17,17.78 216.53,17.15 216.53,14.61 215.9,13.97 | SV11.26 217.17,81.92 217.17,83.19 SV11.25 | SV11.25 216.53,83.82 215.26,83.82 SV11.27 214,83.82 212.72,83.82 SV11.29 | SV10.27 215.9,64.14 215.9,78.11 213.36,80.65 213.36,81.92 212.09,83.19 SV11.29 | SV10.19 225.43,63.5 224.16,63.5 SV10.21 | SV11.21 222.25,83.19 222.25,81.92 SV11.22 222.25,80.65 223.52,79.38 223.52,64.14 SV10.21 | SV11.21 221.62,83.82 220.34,83.82 SV11.23 219.07,83.82 218.44,83.82 | 218.44,83.82 217.81,83.82 SV11.25 | 218.44,83.82 218.44,64.14 SV10.25 | 207.65,83.82 208.91,85.09 211.46,85.09 211.46,83.82 SV11.29 | 207.65,83.82 SV11.33 | U$5.U2 205.1,13.97 205.18,13.97 | U$5.R1 214.63,13.97 214.76,13.97 | U$5.N1 220.98,13.97 221.11,13.97
  Bottom 0.381: U$5.J2 233.68,13.97 233.81,13.97 | U$5.C2 249.56,13.97 249.66,13.97
  pour Bottom (isolate 0.305): 2.54,13.97 2.54,19.05 0,19.05 0,125.73 66.04,125.73 66.04,16.51 59.69,16.51 59.69,13.97
  pour Top (isolate 0.305): 2.54,13.97 2.54,19.05 0,19.05 0,125.73 66.04,125.73 66.04,16.51 59.69,16.51 59.69,13.97
  pour Bottom (isolate 0.305): 68.58,13.97 68.58,19.05 66.04,19.05 66.04,125.73 132.08,125.73 132.08,16.51 125.73,16.51 125.73,13.97
  pour Top (isolate 0.305): 68.58,13.97 68.58,19.05 66.04,19.05 66.04,125.73 132.08,125.73 132.08,16.51 125.73,16.51 125.73,13.97
  pour Bottom (isolate 0.305): 134.62,13.97 134.62,19.05 132.08,19.05 132.08,125.73 198.12,125.73 198.12,16.51 191.77,16.51 191.77,13.97
  pour Top (isolate 0.305): 134.62,13.97 134.62,19.05 132.08,19.05 132.08,125.73 198.12,125.73 198.12,16.51 191.77,16.51 191.77,13.97
  pour Bottom (isolate 0.305): 200.66,13.97 200.66,19.05 198.12,19.05 198.12,125.73 260.35,125.73 260.35,16.51 257.81,16.51 257.81,13.97
  pour Top (isolate 0.305): 200.66,13.97 200.66,19.05 198.12,19.05 198.12,125.73 260.35,125.73 260.35,16.51 257.81,16.51 257.81,13.97
H1
  Top 0.381: 40.64,39.37 40.64,15.24 40.01,14.61 40.01,13.97 U$2.H1 | 40.64,39.37 40.64,38.74 | 40.64,39.37 38.1,39.37 38.1,40.01 37.47,40.64 SV1.26
  Bottom 0.381: SV1.26 36.83,41.28 34.29,43.82 34.29,78.11 31.75,80.65 SV4.16
H2
  Bottom 0.381: SV3.12 38.1,60.33 38.1,42.55 39.37,41.28 SV1.28 39.37,40.01 38.1,38.74 38.1,13.97 U$2.H2
H3
  Bottom 0.381: SV2.12 104.14,60.33 104.14,42.55 105.41,41.28 SV6.28 105.41,40.01 104.14,38.74 104.14,13.97 U$3.H2
H4
  Top 0.381: 106.68,39.37 106.68,15.24 106.05,14.61 106.05,13.97 U$3.H1 | 106.68,39.37 106.68,38.74 | 106.68,39.37 104.14,39.37 104.14,40.01 103.5,40.64 SV6.26
  Bottom 0.381: SV6.26 102.87,41.28 100.33,43.82 100.33,78.11 97.79,80.65 SV5.16
H5
  Bottom 0.381: SV7.12 170.18,60.33 170.18,42.55 171.45,41.28 SV9.28 171.45,40.01 170.18,38.74 170.18,13.97 U$1.H2
H6
  Top 0.381: 172.72,39.37 172.72,15.24 172.09,14.61 172.09,13.97 U$1.H1 | 172.72,39.37 172.72,38.74 | 172.72,39.37 170.18,39.37 170.18,40.01 169.54,40.64 SV9.26
  Bottom 0.381: SV9.26 168.91,41.28 166.37,43.82 166.37,78.11 163.83,80.65 SV8.16
H7
  Bottom 0.381: SV10.12 236.22,60.33 236.22,42.55 237.49,41.28 SV12.28 237.49,40.01 236.22,38.74 236.22,13.97 U$5.H2
H8
  Top 0.381: 238.76,39.37 238.76,15.24 238.12,14.61 238.12,13.97 U$5.H1 | 238.76,39.37 238.76,38.74 | 238.76,39.37 236.22,39.37 236.22,40.01 235.59,40.64 SV12.26
  Bottom 0.381: SV12.26 234.95,41.28 232.41,43.82 232.41,78.11 229.87,80.65 SV11.16
J1
  Top 0.381: SV1.22 31.75,40.01 33.02,38.74 33.02,37.47 34.29,36.2 34.29,14.61 34.92,13.97 U$2.J1
  Bottom 0.381: SV1.22 31.75,41.28 29.21,43.82 29.21,78.11 26.67,80.65 SV4.20
J2
  Top 0.381: SV6.22 97.79,40.01 99.06,38.74 99.06,37.47 100.33,36.2 100.33,14.61 100.97,13.97 U$3.J1
  Bottom 0.381: SV6.22 97.79,41.28 95.25,43.82 95.25,78.11 92.71,80.65 SV5.20
J3
  Top 0.381: SV9.22 163.83,40.01 165.1,38.74 165.1,37.47 166.37,36.2 166.37,14.61 167,13.97 U$1.J1
  Bottom 0.381: SV9.22 163.83,41.28 161.29,43.82 161.29,78.11 158.75,80.65 SV8.20
J4
  Top 0.381: SV12.22 229.87,40.01 231.14,38.74 231.14,37.47 232.41,36.2 232.41,14.61 233.04,13.97 U$5.J1
  Bottom 0.381: SV12.22 229.87,41.28 227.33,43.82 227.33,78.11 224.79,80.65 SV11.20
K1
  Bottom 0.381: SV2.16 99.06,60.33 99.06,42.55 100.33,41.28 SV6.24 100.33,40.01 99.06,38.74 99.06,13.97 U$3.K2
K2
  Bottom 0.381: SV3.16 33.02,60.33 33.02,42.55 34.29,41.28 SV1.24 34.29,40.01 33.02,38.74 33.02,13.97 U$2.K2
K3
  Bottom 0.381: SV7.16 165.1,60.33 165.1,42.55 166.37,41.28 SV9.24 166.37,40.01 165.1,38.74 165.1,13.97 U$1.K2
K4
  Bottom 0.381: SV10.16 231.14,60.33 231.14,42.55 232.41,41.28 SV12.24 232.41,40.01 231.14,38.74 231.14,13.97 U$5.K2
L1
  Top 0.381: 30.48,39.37 30.48,14.61 30.48,13.97 U$2.L1 | 30.48,39.37 30.48,38.74 | 30.48,39.37 27.94,39.37 27.94,40.01 27.3,40.64 SV1.18
  Bottom 0.381: SV1.18 26.67,41.28 24.13,43.82 24.13,78.11 21.59,80.65 SV4.24
L2
  Top 0.381: 96.52,39.37 96.52,14.61 96.52,13.97 U$3.L1 | 96.52,39.37 96.52,38.74 | 96.52,39.37 93.98,39.37 93.98,40.01 93.34,40.64 SV6.18
  Bottom 0.381: SV6.18 92.71,41.28 90.17,43.82 90.17,78.11 87.63,80.65 SV5.24
L3
  Top 0.381: 162.56,39.37 162.56,14.61 162.56,13.97 U$1.L1 | 162.56,39.37 162.56,38.74 | 162.56,39.37 160.02,39.37 160.02,40.01 159.38,40.64 SV9.18
  Bottom 0.381: SV9.18 158.75,41.28 156.21,43.82 156.21,78.11 153.67,80.65 SV8.24
L4
  Top 0.381: 228.6,39.37 228.6,14.61 228.6,13.97 U$5.L1 | 228.6,39.37 228.6,38.74 | 228.6,39.37 226.06,39.37 226.06,40.01 225.43,40.64 SV12.18
  Bottom 0.381: SV12.18 224.79,41.28 222.25,43.82 222.25,78.11 219.71,80.65 SV11.24
M1
  Top 0.381: SV1.14 21.59,40.01 22.86,38.74 22.86,37.47 24.77,35.56 24.77,14.61 25.4,13.97 U$2.M1
  Bottom 0.381: SV1.14 21.59,41.28 19.05,43.82 19.05,78.11 16.51,80.65 SV4.28
M2
  Bottom 0.381: SV3.20 27.94,60.33 27.94,42.55 29.21,41.28 SV1.20 29.21,40.01 27.94,38.74 27.94,14.61 27.3,13.97 U$2.M2
M3
  Bottom 0.381: SV2.20 93.98,60.33 93.98,42.55 95.25,41.28 SV6.20 95.25,40.01 93.98,38.74 93.98,14.61 93.34,13.97 U$3.M2
M4
  Top 0.381: SV6.14 87.63,40.01 88.9,38.74 88.9,37.47 90.81,35.56 90.81,14.61 91.44,13.97 U$3.M1
  Bottom 0.381: SV6.14 87.63,41.28 85.09,43.82 85.09,78.11 82.55,80.65 SV5.28
M5
  Bottom 0.381: SV7.20 160.02,60.33 160.02,42.55 161.29,41.28 SV9.20 161.29,40.01 160.02,38.74 160.02,14.61 159.38,13.97 U$1.M2
M6
  Top 0.381: SV9.14 153.67,40.01 154.94,38.74 154.94,37.47 156.84,35.56 156.84,14.61 157.48,13.97 U$1.M1
  Bottom 0.381: SV9.14 153.67,41.28 151.13,43.82 151.13,78.11 148.59,80.65 SV8.28
M7
  Bottom 0.381: SV10.20 226.06,60.33 226.06,42.55 227.33,41.28 SV12.20 227.33,40.01 226.06,38.74 226.06,14.61 225.43,13.97 U$5.M2
M8
  Top 0.381: SV12.14 219.71,40.01 220.98,38.74 220.98,37.47 222.88,35.56 222.88,14.61 223.52,13.97 U$5.M1
  Bottom 0.381: SV12.14 219.71,41.28 217.17,43.82 217.17,78.11 214.63,80.65 SV11.28
P1
  Top 0.381: SV1.10 16.51,40.01 17.78,38.74 17.78,37.47 18.41,36.83 18.41,14.61 19.05,13.97 U$2.P1
  Bottom 0.381: SV1.10 16.51,41.28 16.51,78.11 13.97,80.65 SV4.30
P2
  Bottom 0.381: SV3.24 22.86,60.33 22.86,42.55 24.13,41.28 SV1.16 24.13,40.01 22.86,38.74 22.86,16.51 20.95,14.61 20.95,13.97 U$2.P2
P3
  Bottom 0.381: SV2.24 88.9,60.33 88.9,42.55 90.17,41.28 SV6.16 90.17,40.01 88.9,38.74 88.9,16.51 87,14.61 87,13.97 U$3.P2
P4
  Top 0.381: SV6.10 82.55,40.01 83.82,38.74 83.82,37.47 84.45,36.83 84.45,14.61 85.09,13.97 U$3.P1
  Bottom 0.381: SV6.10 82.55,41.28 82.55,78.11 80.01,80.65 SV5.30
P5
  Bottom 0.381: SV7.24 154.94,60.33 154.94,42.55 156.21,41.28 SV9.16 156.21,40.01 154.94,38.74 154.94,16.51 153.03,14.61 153.03,13.97 U$1.P2
P6
  Top 0.381: SV9.10 148.59,40.01 149.86,38.74 149.86,37.47 150.5,36.83 150.5,14.61 151.13,13.97 U$1.P1
  Bottom 0.381: SV9.10 148.59,41.28 148.59,78.11 146.05,80.65 SV8.30
P7
  Bottom 0.381: SV10.24 220.98,60.33 220.98,42.55 222.25,41.28 SV12.16 222.25,40.01 220.98,38.74 220.98,16.51 219.07,14.61 219.07,13.97 U$5.P2
P8
  Top 0.381: SV12.10 214.63,40.01 215.9,38.74 215.9,37.47 216.53,36.83 216.53,14.61 217.17,13.97 U$5.P1
  Bottom 0.381: SV12.10 214.63,41.28 214.63,78.11 212.09,80.65 SV11.30
S1
  Top 0.381: SV1.6 11.43,40.01 11.43,39.37 14.61,39.37 15.24,38.74 15.24,15.24 14.61,14.61 14.61,13.97 U$2.S1
  Bottom 0.381: SV1.6 11.43,41.28 13.97,43.82 13.97,78.11 11.43,80.65 SV4.32
S2
  Bottom 0.381: SV3.28 17.78,60.33 17.78,42.55 19.05,41.28 SV1.12 19.05,40.01 17.78,38.74 17.78,17.78 14.61,14.61 14.61,13.97 U$2.S2
S3
  Bottom 0.381: SV2.28 83.82,60.33 83.82,42.55 85.09,41.28 SV6.12 85.09,40.01 83.82,38.74 83.82,17.78 80.64,14.61 80.64,13.97 U$3.S2
S4
  Top 0.381: SV6.6 77.47,40.01 77.47,39.37 80.64,39.37 81.28,38.74 81.28,15.24 80.64,14.61 80.64,13.97 U$3.S1
  Bottom 0.381: SV6.6 77.47,41.28 80.01,43.82 80.01,78.11 77.47,80.65 SV5.32
S5
  Bottom 0.381: SV7.28 149.86,60.33 149.86,42.55 151.13,41.28 SV9.12 151.13,40.01 149.86,38.74 149.86,17.78 146.69,14.61 146.69,13.97 U$1.S2
S6
  Top 0.381: SV9.6 143.51,40.01 143.51,39.37 146.69,39.37 147.32,38.74 147.32,15.24 146.69,14.61 146.69,13.97 U$1.S1
  Bottom 0.381: SV9.6 143.51,41.28 146.05,43.82 146.05,78.11 143.51,80.65 SV8.32
S7
  Bottom 0.381: SV10.28 215.9,60.33 215.9,42.55 217.17,41.28 SV12.12 217.17,40.01 215.9,38.74 215.9,17.78 212.72,14.61 212.72,13.97 U$5.S2
S8
  Top 0.381: SV12.6 209.55,40.01 209.55,39.37 212.72,39.37 213.36,38.74 213.36,15.24 212.72,14.61 212.72,13.97 U$5.S1
  Bottom 0.381: SV12.6 209.55,41.28 212.09,43.82 212.09,78.11 209.55,80.65 SV11.32
T1
  Bottom 0.381: SV2.30 81.28,60.33 81.28,42.55 80.01,41.28 SV6.8 80.01,40.01 78.74,38.74 78.74,15.88 77.47,14.61 77.47,13.97 U$3.T2
T2
  Bottom 0.381: SV3.30 15.24,60.33 15.24,42.55 13.97,41.28 SV1.8 13.97,40.01 12.7,38.74 12.7,15.88 11.43,14.61 11.43,13.97 U$2.T2
T3
  Bottom 0.381: SV7.30 147.32,60.33 147.32,42.55 146.05,41.28 SV9.8 146.05,40.01 144.78,38.74 144.78,15.88 143.51,14.61 143.51,13.97 U$1.T2
T4
  Bottom 0.381: SV10.30 213.36,60.33 213.36,42.55 212.09,41.28 SV12.8 212.09,40.01 210.82,38.74 210.82,15.88 209.55,14.61 209.55,13.97 U$5.T2
V1
  Bottom 0.381: SV2.32 78.74,60.33 78.74,45.09 74.93,41.28 SV6.4 74.93,40.01 73.66,38.74 73.66,17.15 71.12,14.61 71.12,13.97 U$3.V2
V2
  Bottom 0.381: SV3.32 12.7,60.33 12.7,45.09 8.89,41.28 SV1.4 8.89,40.01 7.62,38.74 7.62,17.15 5.08,14.61 5.08,13.97 U$2.V2
V3
  Bottom 0.381: SV7.32 144.78,60.33 144.78,45.09 140.97,41.28 SV9.4 140.97,40.01 139.7,38.74 139.7,17.15 137.16,14.61 137.16,13.97 U$1.V2
V4
  Bottom 0.381: SV10.32 210.82,60.33 210.82,45.09 207.01,41.28 SV12.4 207.01,40.01 205.74,38.74 205.74,17.15 203.2,14.61 203.2,13.97 U$5.V2

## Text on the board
tNames: A1 | A1 | A1 | A1 | V1 | V1 | V1 | V1
tValues: Side 1 | Side 1 | Side 1 | Side 1 | Side 2 | Side 2 | Side 2 | Side 2 | BC08J | BC08J | BC08J | BC08J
